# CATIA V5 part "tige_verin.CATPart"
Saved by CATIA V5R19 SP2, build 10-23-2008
Part number: tige_verin
Bounding box of the stored display mesh (mm): x -50 to 60, y -21.35 to 786.271, z -30 to 30
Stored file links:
  C:\Users\matthieu\Desktop\IAO\modele_CAO\tige_verin.CATPart
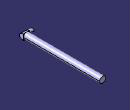
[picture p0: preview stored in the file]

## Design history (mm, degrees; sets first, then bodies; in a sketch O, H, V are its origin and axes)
Parameters
  Longueur_tige_verin = 766.2711 mm
Body1 (main body)
  Sketch1 on yz-plane, origin (0, 0, 0), H (0, 1, 0), V (0, 0, 1)
    circle A1 centre (0, 0) radius 15
    line L1 (20, -30) -> (20, 30)
    line L2 (20, 30) -> (-7.3023, 20.0628)
    arc A2 centre (0, 0) radius 21.3504 from (-7.3023, 20.0628) to (-7.3023, -20.0628) ccw
    line L3 (-7.3023, -20.0628) -> (20, -30)
    radius A1 = 15
    length L1 = 60
    angle L2 L1 = 70
    angle L3 L1 = 70
    distance L1 V = 20
    vertical: L1 V
    tangency: A2 L2, L3 A2
    concentricity: A2 A1
  MultiPad1: profile Sketch1, domains (length 60; length 60 / length 50)
  Sketch2 on face of MultiPad1 from Sketch1.L1, origin (0, 20, 0), H (-1, 0, 0), V (0, 0, 1)
    circle A1 centre (-30, 0) radius 30
    point P1 (-30, 0)
    distance V P1 = 30
    coincidence: A1 O, P1 H
  Pad1: profile Sketch2, direction (0, 1, 0), length 766.2711 {= Longueur_tige_verin}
